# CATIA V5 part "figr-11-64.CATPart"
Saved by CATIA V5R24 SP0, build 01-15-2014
Part number: Part1
Bounding box of the stored display mesh (mm): x -54 to 54, y -91.936 to 93.838, z -12.649 to 110.643
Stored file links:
  D:\KAVITA\CATIA V5-6R2014 Project_ Kavita\CATIA V5-6R2014_partfiles\Partfiles\c11_catia_v5-6r2014_prt\figr-11-64.CATPart
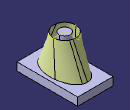
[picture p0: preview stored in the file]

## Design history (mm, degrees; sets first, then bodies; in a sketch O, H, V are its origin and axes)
Set1
  Loft1: Sections (Sketch4; Sketch3)
Body1 (main body)
  Sketch1 on yz-plane, origin (0, 0, 0), H (0, 1, 0), V (0, 0, 1)
    point P1 (93.8379, 11.643)
    line L1 (93.8379, 11.643) -> (93.8379, -12.6487)
    line L2 (93.8379, -12.6487) -> (-91.9362, -12.6487)
    line L3 (-91.9362, -12.6487) -> (-91.9362, 11.643)
    line L4 (-91.9362, 11.643) -> (93.8379, 11.643)
    point P5 (93.8379, 11.643)
    vertical: L1 V, L3 V
    horizontal: L2 H, L4 H
    coincidence: P5 P1
  Pad1: profile Sketch1, direction (1, 0, 0), length 54, mirrored extent
  Sketch2 on face of Pad1, origin (0, 0, 11.643), H (1, 0, 0), V (0, 1, 0)
    circle A1 centre (0, 0) radius 16.7533
    point P1 (16.7533, 0)
    coincidence: A1 P1, P1 H
  Pad2: profile Sketch2, direction (0, 0, 1), length 99
  Sketch3 on face of Pad2, origin (0, 0, 110.643), H (1, 0, 0), V (0, 1, 0)
    point P1 (0, 42.8937)
    point P2 (33.9651, 0)
    projected circle E1 centre (0, 0) radius 16.7533 from edge [face of Pad2 | face of Pad2]
    circle A1 centre (0, 0) radius 33.9651
    point P3 (0, 33.9651)
    coincidence: P1 V, P2 H, A1 P2, A1 P3, P3 V
  Sketch4 on face of Pad1, origin (0, 0, 11.643), H (1, 0, 0), V (0, 1, 0)
    ellipse A1 centre (0, 0) semi-axes 69.9141, 43.1918 rotation 90
    point P1 (0, 69.9141)
    point P2 (43.1918, 0)
    coincidence: P1 V, P2 H, A1 P1, A1 P2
